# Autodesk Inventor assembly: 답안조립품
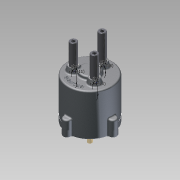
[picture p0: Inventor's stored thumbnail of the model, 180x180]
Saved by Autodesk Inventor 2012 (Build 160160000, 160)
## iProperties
Created: 2015-05
Part Number: 답안조립품
Document SubType Name: Assembly
Designer: Administrator
Mass: 2160.25 g
Surface Area: 1801.24 cm^2
Volume: 438.524 cm^3
Density: 4.92619 g/cm^3
Author: Administrator
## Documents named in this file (14)
- C:\Inventor1급\2014-02-20 1급 공용부품\답안조립품.iam
- C:\Inventor1급\2014-02-20 1급 공용부품\몸체.ipt
- C:\Inventor1급\2014-02-20 1급 공용부품\커버.ipt
- C:\Inventor1급\2014-02-20 1급 공용부품\오일실.ipt
- C:\Inventor1급\2014-02-20 1급 공용부품\베어링 NA 4900.ipt
- C:\Inventor1급\2014-02-20 1급 공용부품\메인 축.ipt
- C:\Inventor1급\2014-02-20 1급 공용부품\멈춤링 22 x 1.2.ipt
- C:\Inventor1급\2014-02-20 1급 공용부품\판캠.ipt
- C:\Inventor1급\2014-02-20 1급 공용부품\슬라이드 축.ipt
- C:\Inventor1급\2014-02-20 1급 공용부품\가변 스프링-01.ipt
- C:\Inventor1급\2014-02-20 1급 공용부품\가변 스프링-02.ipt
- C:\Inventor1급\2014-02-20 1급 공용부품\가변 스프링-03.ipt
- C:\Inventor1급\2014-02-20 1급 공용부품\M5x0.5x20.ipt
- C:\Inventor1급\2014-02-20 1급 공용부품\멈춤링 10 x 1.ipt
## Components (7 placed, 4 different names)
1. 가변 스프링-01:1
2. 가변 스프링-02:1
3. 가변 스프링-03:1
4. M5x0.5x20:1
5. M5x0.5x20:2
6. M5x0.5x20:3
7. M5x0.5x20:4
